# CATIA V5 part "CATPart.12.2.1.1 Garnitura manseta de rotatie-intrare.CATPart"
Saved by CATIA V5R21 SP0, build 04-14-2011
Part number: Garnitura manseta de rotatie.3
Bounding box of the stored display mesh (mm): x 1.667 to 11.667, y -24.997 to 24.997, z -24.865 to 24.865
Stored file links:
  C:\Users\MIRCEA\Desktop\MOM\Mogan\model\CATPart.12.2.1.1 Garnitura manseta de rotatie-intrare.CATPart
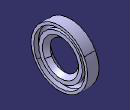
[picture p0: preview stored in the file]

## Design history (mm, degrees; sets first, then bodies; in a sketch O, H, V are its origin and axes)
Parameters
  d = 30 mm
  D = 50 mm
  h = 10 mm
Body1 (main body)
  Sketch1 on xy-plane, origin (0, 0, 0), H (1, 0, 0), V (0, 1, 0)
    point P1 (1.6667, 25)
    line L1 (1.6667, 25) -> (11.6667, 25)
    point P2 (11.6667, 25)
    line L2 (11.6667, 25) -> (11.6667, 22.6667)
    line L3 (11.6667, 22.6667) -> (7.5301, 22.6667)
    arc A1 centre (5.6667, 21) radius 2.5 from (7.5301, 22.6667) to (7.5301, 19.3333) ccw
    point P5 (5.6667, 21)
    point P6 (7.5301, 22.6667)
    line L4 (7.5301, 19.3333) -> (10.6667, 19.3333)
    point P9 (1.6667, 25)
    point P10 (11.6667, 25)
    point P11 (11.6667, 25)
    line L5 (10.6667, 19.3333) -> (10.6667, 16)
    point P12 (10.6667, 16)
    line L6 (10.6667, 16) -> (7.3333, 12.6667)
    point P13 (7.3333, 12.6667)
    line L7 (7.3333, 12.6667) -> (1.6667, 18.3333)
    line L8 (1.6667, 18.3333) -> (1.6667, 25)
    distance P1 H = 25 {= D /2}
    radius A1 = 2.5 {= h/4}
    distance P1 P2 = 10 {= h}
    angle L6 H = 135
    distance P12 H = 16 {= d /2+1 mm}
    distance P5 H = 21 {= (D+d)/4+ 1mm}
    distance L4 H = 19.3333 {= Sketch1.distance(P5 H) - Sketch1.radius(A1) /1.5}
    distance L3 H = 22.6667 {= Sketch1.distance(P5 H) +Sketch1.radius(A1) /1.5}
    distance P13 L5 = 3.3333 {= h/3}
    distance P5 L8 = 4 {= h/2.5}
    distance L5 L2 = 1
    horizontal: L1 H, L3 H, L4 H
    vertical: L2 V, L5 V, L8 V
    coincidence: A1 P6, P6 L3, L1 P1, L1 P2, L2 P2, P11 P2, P10 P2, P9 P1
    perpendicularity: L7 L6
  Shaft1: profile Sketch1, axis Sketch1.H, angle 360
